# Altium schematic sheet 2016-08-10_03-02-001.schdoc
size 326 x 125 mm; SheetNumber: 1; SheetTotal: 1
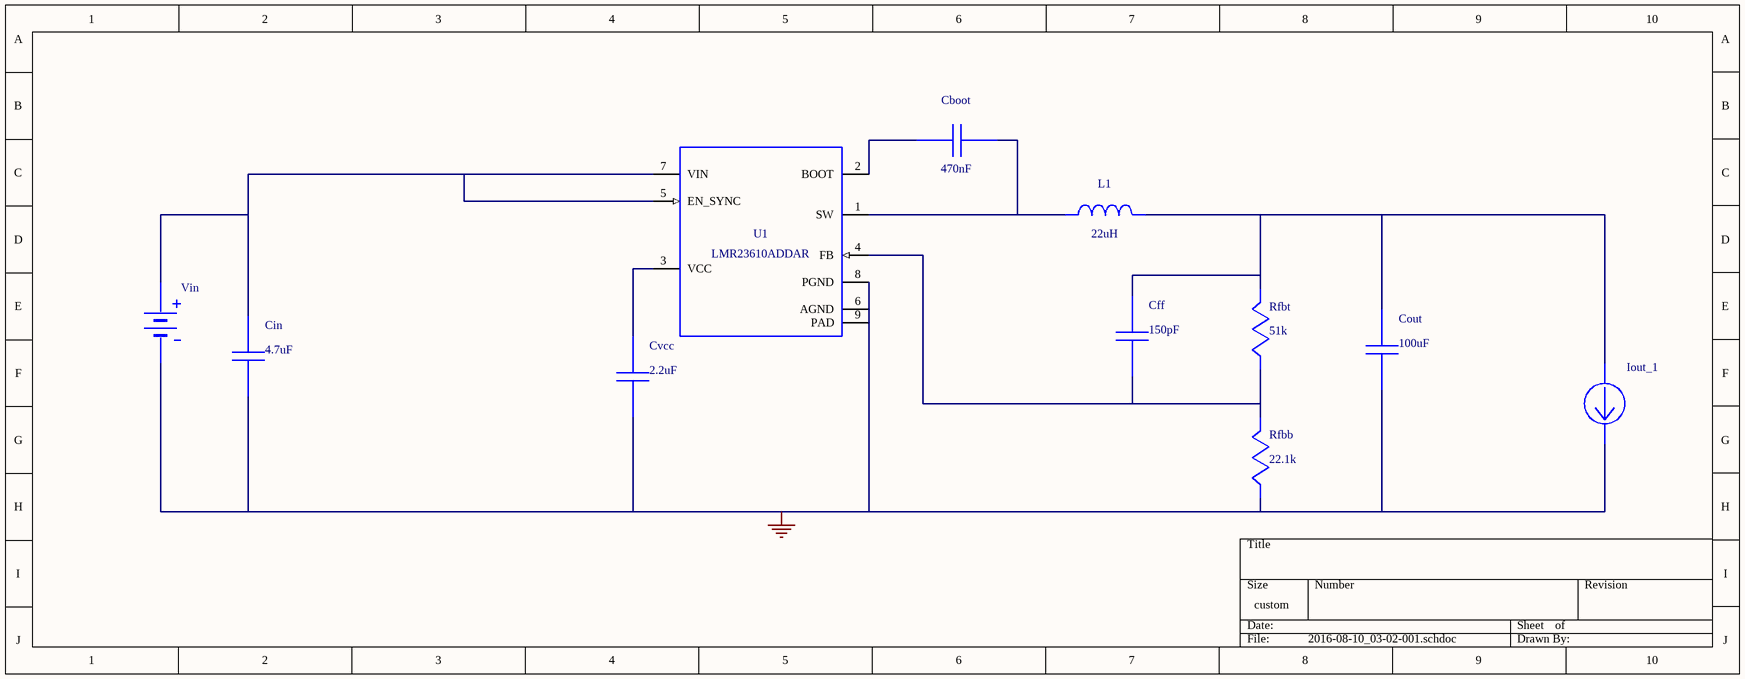
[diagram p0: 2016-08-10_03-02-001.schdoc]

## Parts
Cboot  value 470nF  (hidden comment: UMK212B7474KG-T)
Cff  value 150pF  (hidden comment: C0603C151K3GACTU)
Cin  value 4.7uF  (hidden comment: GRM32ER71H475KA88L)
Cout  value 100uF  (hidden comment: GRM31CR60J107ME39L)
Cvcc  value 2.2uF  (hidden comment: GRM188R60J225KE19D)
Iout_1  WB_CURRENT_LOAD  (value not drawn)
L1  value 22uH  (hidden comment: SRN6045-220M)
Rfbb  value 22.1k  (hidden comment: ERJ-6ENF2212V)
Rfbt  value 51k  (hidden comment: RC0603FR-0751KL)
U1  LMR23610ADDAR
Vin  WB_BATTERY  (value not drawn)

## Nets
0: Cin.2 Cout.2 Cvcc.2 Iout_1.2(-) Rfbb.2 U1.6(AGND) U1.8(PGND) U1.9(PAD) Vin.2(-)
NetCboot_1: Cboot.1 U1.2(BOOT)
NetCboot_2: Cboot.2 L1.1 U1.1(SW)
NetCff_1: Cff.1 Cout.1 Iout_1.1(+) L1.2 Rfbt.1
NetCff_2: Cff.2 Rfbb.1 Rfbt.2 U1.4(FB)
NetCin_1: Cin.1 U1.5(EN_SYNC) U1.7(VIN) Vin.1(+)
NetCvcc_1: Cvcc.1 U1.3(VCC)

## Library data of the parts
Cboot = UMK212B7474KG-T: Manufacturer Name: Taiyo Yuden
Cff = C0603C151K3GACTU: Manufacturer Name: Kemet
Cin = GRM32ER71H475KA88L: GRM32ER71H475KA8; Manufacturer Name: MuRata
Cout = GRM31CR60J107ME39L: GRM31CR60J107ME3; Manufacturer Name: MuRata
Cvcc = GRM188R60J225KE19D: GRM188R60J225KE1; Manufacturer Name: MuRata
L1 = SRN6045-220M: Manufacturer Name: Bourns
Rfbb = ERJ-6ENF2212V: Manufacturer Name: Panasonic
Rfbt = RC0603FR-0751KL: Manufacturer Name: Yageo America
U1 = LMR23610ADDAR: Manufacturer Name: Texas Instruments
